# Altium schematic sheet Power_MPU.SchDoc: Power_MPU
size A3; CompanyName: STMicroelectronics; DocumentNumber: MB1272; Revision: A-01; SheetNumber: 4; SheetTotal: 15; Project: STM32MP15-DISCO PI
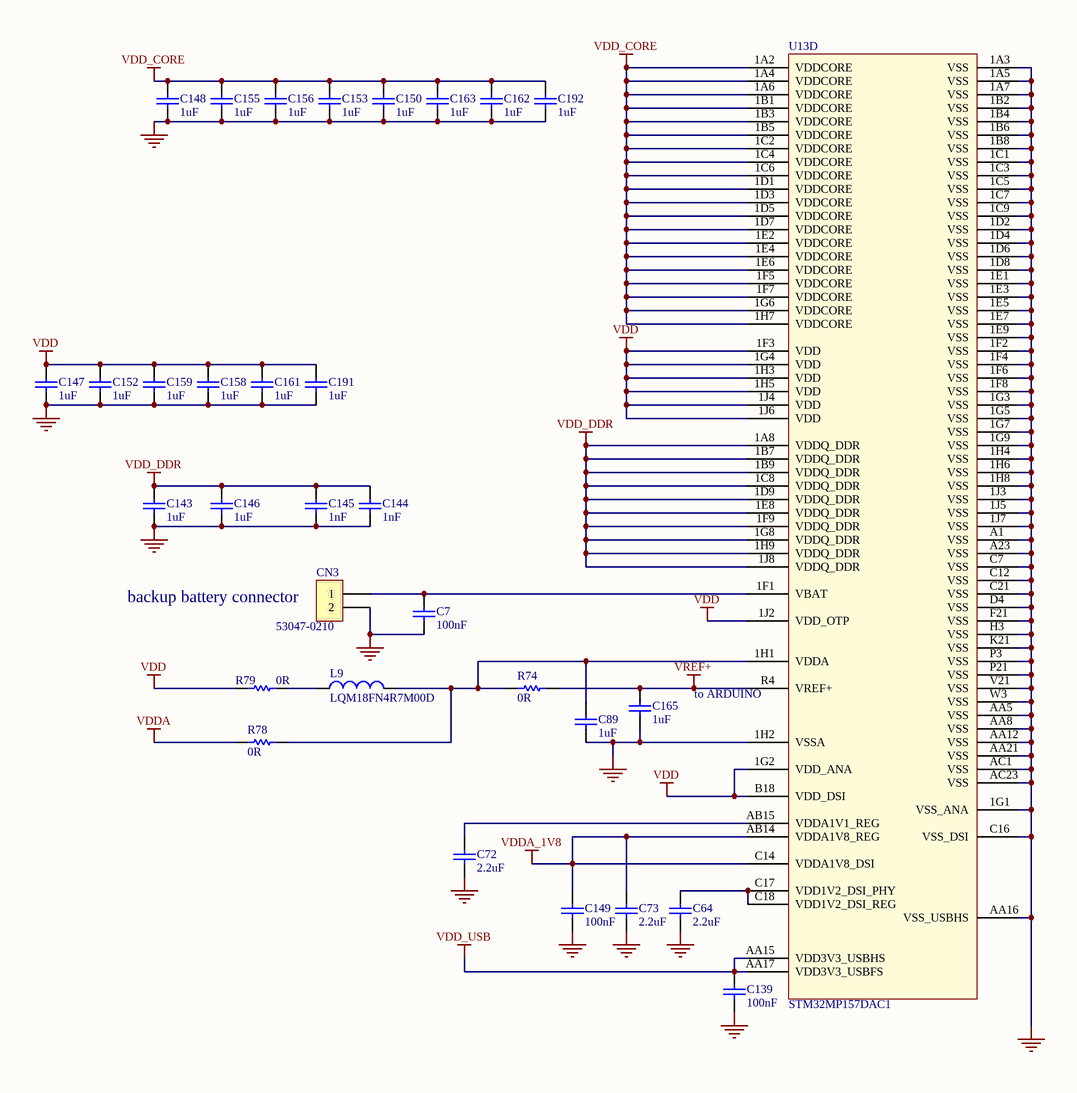
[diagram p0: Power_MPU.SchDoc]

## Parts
C7  value 100nF  [C0402]
C64  value 2.2uF  [C0402]  (hidden comment: Capacitor)
C72  value 2.2uF  [C0402]  (hidden comment: Capacitor)
C73  value 2.2uF  [C0402]  (hidden comment: Capacitor)
C89  value 1uF  [C0402]
C139  value 100nF  [C0402]
C143  value 1uF  [C0402]
C144  value 1nF  [C0402]
C145  value 1nF  [C0402]
C146  value 1uF  [C0402]
C147  value 1uF  [C0402]
C148  value 1uF  [C0402]
C149  value 100nF  [C0402]
C150  value 1uF  [C0402]
C152  value 1uF  [C0402]
C153  value 1uF  [C0402]
C155  value 1uF  [C0402]
C156  value 1uF  [C0402]
C158  value 1uF  [C0402]
C159  value 1uF  [C0402]
C161  value 1uF  [C0402]
C162  value 1uF  [C0402]
C163  value 1uF  [C0402]
C165  value 1uF  [C0402]
C191  value 1uF  [C0402]
C192  value 1uF  [C0402]
CN3  value 53047-0210  [CON_MOLEX_53047-0210]
L9  LQM18FN4R7M00D  [L0603]
R74  value 0R  [R0402]
R78  value 0R  [R0402]
R79  value 0R  [R0402]
U13  value STM32MP157DAC1  [ICC_TFBGA361_12X12_STM32MP157CAC3_P050-065]  (part D of 5)

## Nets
GND: C7.1 C64.2 C72.2 C73.2 C89.1 C139.1 C143.1 C144.1 C145.1 C146.1 C147.1 C148.1 C149.1 C150.1 C152.1 C153.1 C155.1 C156.1 C158.1 C159.1 C161.1 C162.1 C163.1 C165.1 C191.1 C192.1 CN3.2 U13.1A3(VSS) U13.1A5(VSS) U13.1A7(VSS) U13.1B2(VSS) U13.1B4(VSS) U13.1B6(VSS) U13.1B8(VSS) U13.1C1(VSS) U13.1C3(VSS) U13.1C5(VSS) U13.1C7(VSS) U13.1C9(VSS) U13.1D2(VSS) U13.1D4(VSS) U13.1D6(VSS) U13.1D8(VSS) U13.1E1(VSS) U13.1E3(VSS) U13.1E5(VSS) U13.1E7(VSS) U13.1E9(VSS) U13.1F2(VSS) U13.1F4(VSS) U13.1F6(VSS) U13.1F8(VSS) U13.1G1(VSS_ANA) U13.1G3(VSS) U13.1G5(VSS) U13.1G7(VSS) U13.1G9(VSS) U13.1H2(VSSA) U13.1H4(VSS) U13.1H6(VSS) U13.1H8(VSS) U13.1J3(VSS) U13.1J5(VSS) U13.1J7(VSS) U13.A1(VSS) U13.A23(VSS) U13.AA5(VSS) U13.AA8(VSS) U13.AA12(VSS) U13.AA16(VSS_USBHS) U13.AA21(VSS) U13.AC1(VSS) U13.AC23(VSS) U13.C7(VSS) U13.C12(VSS) U13.C16(VSS_DSI) U13.C21(VSS) U13.D4(VSS) U13.F21(VSS) U13.H3(VSS) U13.K21(VSS) U13.P3(VSS) U13.P21(VSS) U13.V21(VSS) U13.W3(VSS)
VDD: C147.2 C152.2 C158.2 C159.2 C161.2 C191.2 R79.1 U13.1F3(VDD) U13.1G2(VDD_ANA) U13.1G4(VDD) U13.1H3(VDD) U13.1H5(VDD) U13.1J2(VDD_OTP) U13.1J4(VDD) U13.1J6(VDD) U13.B18(VDD_DSI)
VDD_CORE: C148.2 C150.2 C153.2 C155.2 C156.2 C162.2 C163.2 C192.2 U13.1A2(VDDCORE) U13.1A4(VDDCORE) U13.1A6(VDDCORE) U13.1B1(VDDCORE) U13.1B3(VDDCORE) U13.1B5(VDDCORE) U13.1C2(VDDCORE) U13.1C4(VDDCORE) U13.1C6(VDDCORE) U13.1D1(VDDCORE) U13.1D3(VDDCORE) U13.1D5(VDDCORE) U13.1D7(VDDCORE) U13.1E2(VDDCORE) U13.1E4(VDDCORE) U13.1E6(VDDCORE) U13.1F5(VDDCORE) U13.1F7(VDDCORE) U13.1G6(VDDCORE) U13.1H7(VDDCORE)
VDD_DDR: C143.2 C144.2 C145.2 C146.2 U13.1A8(VDDQ_DDR) U13.1B7(VDDQ_DDR) U13.1B9(VDDQ_DDR) U13.1C8(VDDQ_DDR) U13.1D9(VDDQ_DDR) U13.1E8(VDDQ_DDR) U13.1F9(VDDQ_DDR) U13.1G8(VDDQ_DDR) U13.1H9(VDDQ_DDR) U13.1J8(VDDQ_DDR)
VDD_USB: C139.2 U13.AA15(VDD3V3_USBHS) U13.AA17(VDD3V3_USBFS)
VDDA: R78.1
VDDA_1V8: C73.1 C149.2 U13.AB14(VDDA1V8_REG) U13.C14(VDDA1V8_DSI)
VREF+: C165.2 R74.2 U13.R4(VREF+)
NetC7_2: C7.2 CN3.1 U13.1F1(VBAT)
NetC64_1: C64.1 U13.C17(VDD1V2_DSI_PHY) U13.C18(VDD1V2_DSI_REG)
NetC72_1: C72.1 U13.AB15(VDDA1V1_REG)
NetC89_2: C89.2 L9.2 R74.1 R78.2 U13.1H1(VDDA)
NetL9_1: L9.1 R79.2

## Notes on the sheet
- (near CN3) backup battery connector
- to ARDUINO

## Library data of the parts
C7 C139 C149 = MCD-00006: Capacitor,100nF,16V,X7R,10%,0402; Manufacturer_Part_Number: CC0402KRX7R7BB104; Manufacturer: YAGEO; Alternate_Manufacturer: MURATA; Alternate_Manufacturer_Part_Number: GCM155R71C104KA55D; Provided_By: SUBCO; Initial_Board_Reference: MB1274
C64 C72 C73 = MCD-01823: Capacitor,MLCC,2.2uF,6V3,X5R,10%,0402,T=0.5; Manufacturer_Part_Number: GRM155R60J225KE95D; Manufacturer: MURATA; ECCN_US: EAR99; ECCN_EU: NEC; Provided_By: SUBCO
C89 C143 C146-C148 C150 C152 C153 C155 C156 C158 C159 C161-C163 C165 C191 C192 = MCD-00095: Capacitor,1uF,6V3,X5R,10%,0402; Manufacturer_Part_Number: GRM155R61E105KA12; Manufacturer: MURATA; Alternate_Manufacturer_Part_Number: GRM155R60J105KE19; ECCN_US: EAR99; ECCN_EU: NEC; Provided_By: SUBCO; Initial_Board_Reference: MB1262
C144 C145 = MCD-00198: Capacitor,1nF,16V,X7R,10%,0402; Manufacturer_Part_Number: CC0402KRX7R7BB102; Manufacturer: YAGEO; Provided_By: SUBCO
CN3 = MCD-00655: Header 2 circuits, 1.25mm Pitch ,  Vertical, with Friction Lock; Part_Type: Connector; Manufacturer: MOLEX; Provided_By: SUBCO; Initial_Board_Reference: MB1272
L9 = MCD-01134: IND 4.7µH 20% 80mA 600mhom 0603; Part_Type: Inductor; Manufacturer: MURATA; Provided_By: SUBCO; Initial_Board_Reference: MB1272
R74 R78 = MCD-00052: Resistor,0R,0402,5%,1/16W; Manufacturer_Part_Number: RC0402JR-070RL; Manufacturer: YAGEO; Provided_By: SUBCO; Initial_Board_Reference: MB1274
R79 = MCD-00052: Resistor,0R,0402,5%,1/16W; Manufacturer_Part_Number: RC0402JR-070RL; Manufacturer: YAGEO; Provided_By: SUBCO; Initial_Board_Reference: MB1274; Fitted: NO
U13 = MCD-02020: MPU TFBGA12x12 without crypto increased frequency; Part_Type: IC; Manufacturer: STMICROELECTRONICS; Provided_By: SUBCO with ST control; ECCN_US: 3A991A2; ECCN_EU: NEC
